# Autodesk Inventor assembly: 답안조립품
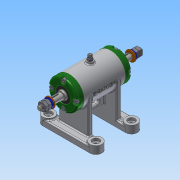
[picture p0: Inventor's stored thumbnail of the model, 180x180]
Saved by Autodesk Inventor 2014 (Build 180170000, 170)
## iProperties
Created: 2015-11
Part Number: 답안조립품
Document SubType Name: Assembly
Designer: 103-08
Author: 103-08
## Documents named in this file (16)
- C:\Users\103-08\Desktop\451110V1027\답안조립품.iam
- C:\Users\103-08\Desktop\451110V1027\본체.ipt
- C:\Users\103-08\Desktop\451110V1027\V벨트풀리.ipt
- C:\Users\103-08\Desktop\451110V1027\너트 M 8.ipt
- C:\Users\103-08\Desktop\451110V1027\니플 M 6 x 0.75.ipt
- C:\Users\103-08\Desktop\451110V1027\베어링 15 x 32 x 9.ipt
- C:\Users\103-08\Desktop\451110V1027\볼트 M 6 x 8.ipt
- C:\Users\103-08\Desktop\451110V1027\볼트 M4 x 12.ipt
- C:\Users\103-08\Desktop\451110V1027\스퍼기어.ipt
- C:\Users\103-08\Desktop\451110V1027\스프링와셔 8.ipt
- C:\Users\103-08\Desktop\451110V1027\오일 실 15 25 7.ipt
- C:\Users\103-08\Desktop\451110V1027\와셔 6x11.5.ipt
- C:\Users\103-08\Desktop\451110V1027\와셔 8x17.ipt
- C:\Users\103-08\Desktop\451110V1027\축.ipt
- C:\Users\103-08\Desktop\451110V1027\커버.ipt
- C:\Users\103-08\Desktop\451110V1027\키 3 x 3 x 12.ipt
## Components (11 placed, 3 different names)
1. V벨트풀리:1 — 각도:4
2. KS B 2023 6002 - 15 x 32 x 9:1
3. KS B 2023 6002 - 15 x 32 x 9:2
4. ISO 4762 M4 x 12:2
5. ISO 4762 M4 x 12:3
6. ISO 4762 M4 x 12:4
7. ISO 4762 M4 x 12:5
8. ISO 4762 M4 x 12:1
9. ISO 4762 M4 x 12:6
10. ISO 4762 M4 x 12:7
11. ISO 4762 M4 x 12:8
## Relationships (1: Angle 1)
- 각도:4 [Angle]: V벨트풀리:1
